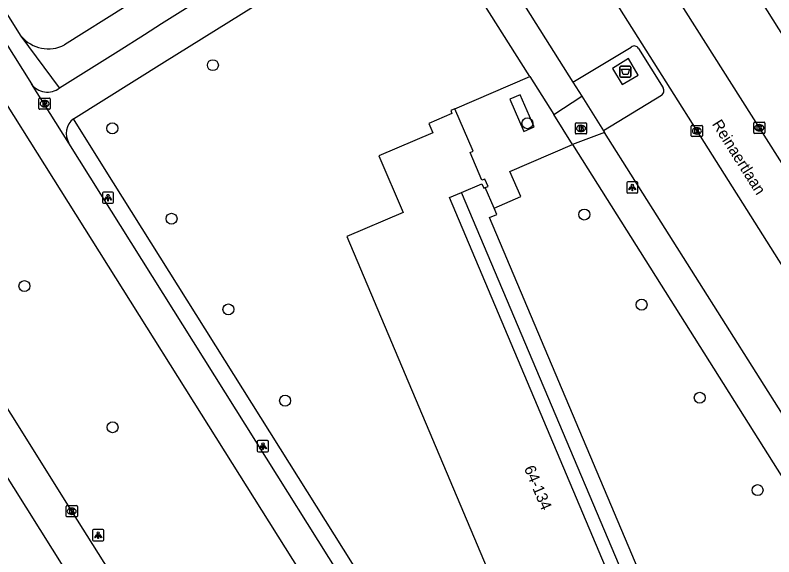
# Model space of a CAD drawing. Extents: x 160077 to 160945, y 386481 to 387498.
# Drawn here: x 160179.2 to 160246.9, y 387158.5 to 387206.8 of the extents above; entities that cross this region are included whole.
import ezdxf

# ---------------------------------------------------------------- set-up
doc = ezdxf.new("R2010")
doc.units = 0
for name, color, linetype in [('IMGEO_Afval_apart_plaats', 7, 'Continuous'), ('IMGEO_Boom', 7, 'Continuous'), ('IMGEO_Brandkraan', 7, 'Continuous'), ('IMGEO_Fietspad_gesloten', 7, 'Continuous'), ('IMGEO_Fietspad_open', 7, 'Continuous'), ('IMGEO_Kolk', 7, 'Continuous'), ('IMGEO_Lichtpunt', 7, 'Continuous'), ('IMGEO_Openbare_ruimte_label', 7, 'Continuous'), ('IMGEO_OVBaan_gesloten', 7, 'Continuous'), ('IMGEO_Pand', 7, 'Continuous'), ('IMGEO_Pand_nummerreeks', 7, 'Continuous'), ('IMGEO_Rijbaan_lokaal_open', 7, 'Continuous'), ('IMGEO_Rijbaan_regionaal_gesloten', 7, 'Continuous'), ('IMGEO_Voetpad_gesloten', 7, 'Continuous'), ('IMGEO_Voetpad_open', 7, 'Continuous')]:
    doc.layers.add(name, color=color, linetype=linetype)

msp = doc.modelspace()

# ---------------------------------------------------------------- linework, layer by layer
at = {"layer": 'IMGEO_Afval_apart_plaats'}
for p, q in [((160233.142, 387201.381), (160233.142, 387202.181)), ((160233.142, 387202.181), (160233.142, 387201.381)), ((160233.242, 387202.281), (160234.032, 387202.281)), ((160234.032, 387202.281), (160233.242, 387202.281)), ((160234.132, 387202.181), (160234.132, 387201.381)), ((160234.132, 387201.381), (160234.132, 387202.181)), ((160234.032, 387201.281), (160233.242, 387201.281)), ((160233.242, 387201.281), (160234.032, 387201.281))]:
    msp.add_line(p, q, dxfattribs=at)
msp.add_lwpolyline([(160233.285, 387201.995), (160233.989, 387201.995), (160233.84, 387201.525), (160233.434, 387201.525), (160233.285, 387201.995)], dxfattribs=at)
for centre, start, end in [((160233.242, 387202.181), 90, 180), ((160233.242, 387202.181), 90, 180), ((160234.032, 387202.181), 0, 90), ((160234.032, 387202.181), 360, 90), ((160233.242, 387201.381), 180, 270), ((160233.242, 387201.381), 180, 270), ((160234.032, 387201.381), 270, 0), ((160234.032, 387201.381), 270, 0)]:
    msp.add_arc(centre, 0.1, start, end, dxfattribs=at)
at = {"layer": 'IMGEO_Boom'}
for centre in [(160196.85, 387202.357), (160224.896, 387197.177), (160187.885, 387196.721), (160229.972, 387189.035), (160193.164, 387188.658), (160180.05, 387182.652), (160235.076, 387180.991), (160198.235, 387180.572), (160240.264, 387172.688), (160203.294, 387172.428), (160187.905, 387170.057), (160245.423, 387164.448)]:
    msp.add_circle(centre, 0.489, dxfattribs=at)
at = {"layer": 'IMGEO_Brandkraan'}
for p, q in [((160181.421, 387199.424), (160182.273, 387199.424)), ((160181.346, 387198.498), (160181.346, 387199.35)), ((160181.834, 387199.204), (160181.859, 387199.204)), ((160182.347, 387199.35), (160182.347, 387198.498)), ((160182.273, 387198.424), (160181.421, 387198.424)), ((160181.857, 387198.644), (160181.832, 387198.644)), ((160229.177, 387196.294), (160229.177, 387197.146)), ((160229.252, 387197.22), (160230.104, 387197.22)), ((160229.665, 387197), (160229.69, 387197)), ((160230.178, 387197.146), (160230.178, 387196.294)), ((160230.104, 387196.22), (160229.252, 387196.22)), ((160229.688, 387196.44), (160229.663, 387196.44))]:
    msp.add_line(p, q, dxfattribs=at)
for points in [[(160181.421, 387199.424), (160182.273, 387199.424)], [(160181.346, 387198.498), (160181.346, 387199.35)], [(160181.694, 387199.124), (160181.694, 387198.724), (160181.907, 387198.724)], [(160181.925, 387199.124), (160181.694, 387199.124)], [(160181.873, 387199.043), (160181.819, 387199.043), (160181.819, 387198.967)], [(160181.819, 387198.967), (160181.872, 387198.967)], [(160181.881, 387198.891), (160181.819, 387198.891), (160181.819, 387198.81)], [(160181.819, 387198.81), (160181.881, 387198.81)], [(160182.347, 387199.35), (160182.347, 387198.498)], [(160182.273, 387198.424), (160181.421, 387198.424)], [(160229.177, 387196.294), (160229.177, 387197.146)], [(160229.252, 387197.22), (160230.104, 387197.22)], [(160229.525, 387196.92), (160229.525, 387196.52), (160229.738, 387196.52)], [(160229.756, 387196.92), (160229.525, 387196.92)], [(160229.704, 387196.839), (160229.65, 387196.839), (160229.65, 387196.763)], [(160229.65, 387196.763), (160229.703, 387196.763)], [(160230.178, 387197.146), (160230.178, 387196.294)], [(160230.104, 387196.22), (160229.252, 387196.22)], [(160229.712, 387196.687), (160229.65, 387196.687), (160229.65, 387196.606)], [(160229.65, 387196.606), (160229.712, 387196.606)]]:
    msp.add_lwpolyline(points, dxfattribs=at)
for centre, radius, start, end in [((160181.423, 387199.348), 0.0765, 91.55205, 178.44795), ((160181.423, 387199.348), 0.0765, 91.55205, 178.44795), ((160182.271, 387199.348), 0.0765, 1.55205, 88.44795), ((160182.271, 387199.348), 0.0765, 1.55205, 88.44795), ((160181.874, 387199.005), 0.0379, 267.82845, 90.93552), ((160181.882, 387198.85), 0.0404, 269.87594, 90.50774), ((160181.913, 387198.975), 0.251, 268.66757, 293.53466), ((160181.929, 387198.979), 0.145, 59.4692, 91.53667), ((160181.954, 387199.026), 0.0922, 285.51372, 58.15012), ((160181.959, 387198.834), 0.105, 301.31148, 78.98903), ((160181.423, 387198.5), 0.0765, 181.55205, 268.44795), ((160181.423, 387198.5), 0.0765, 181.55205, 268.44795), ((160182.271, 387198.5), 0.0765, 271.55205, 358.44795), ((160182.271, 387198.5), 0.0765, 271.55205, 358.44795), ((160229.254, 387197.144), 0.0765, 91.55205, 178.44795), ((160229.254, 387197.144), 0.0765, 91.55205, 178.44795), ((160229.705, 387196.801), 0.0379, 267.82845, 90.93552), ((160229.76, 387196.775), 0.145, 59.4692, 91.53667), ((160229.785, 387196.822), 0.0922, 285.51372, 58.15012), ((160229.79, 387196.63), 0.105, 301.31148, 78.98903), ((160230.102, 387197.144), 0.0765, 1.55205, 88.44795), ((160230.102, 387197.144), 0.0765, 1.55205, 88.44795), ((160229.254, 387196.296), 0.0765, 181.55205, 268.44795), ((160229.254, 387196.296), 0.0765, 181.55205, 268.44795), ((160229.713, 387196.646), 0.0404, 269.87594, 90.50774), ((160229.744, 387196.771), 0.251, 268.66757, 293.53466), ((160230.102, 387196.296), 0.0765, 271.55205, 358.44795), ((160230.102, 387196.296), 0.0765, 271.55205, 358.44795)]:
    msp.add_arc(centre, radius, start, end, dxfattribs=at)
for centre, major_axis, ratio, start_param, end_param in [((160181.833, 387198.924), (-0.387, 0.002), 0.722429, 4.712389, 7.853982), ((160181.858, 387198.924), (-0.39, 0.002), 0.717154, 1.570796, 4.712389), ((160229.664, 387196.72), (-0.387, 0.002), 0.722429, 4.712389, 7.853982), ((160229.689, 387196.72), (-0.39, 0.002), 0.717154, 1.570796, 4.712389)]:
    msp.add_ellipse(centre, major_axis=major_axis, ratio=ratio, start_param=start_param, end_param=end_param, dxfattribs=at)
at = {"layer": 'IMGEO_Fietspad_gesloten'}
for points in [[(160139.072, 387265.739), (160141.59, 387262.907), (160159.923, 387233.732), (160180.666, 387200.687)], [(160136.342, 387264.367), (160139.625, 387260.516), (160141.252, 387258.195), (160161.015, 387226.623), (160198.581, 387166.822), (160220.594, 387131.778)], [(160184.005, 387195.408), (160180.666, 387200.687)], [(160223.762, 387132.086), (160222.926, 387133.369), (160185.895, 387192.376), (160184.005, 387195.408)]]:
    msp.add_lwpolyline(points, dxfattribs=at)
at = {"layer": 'IMGEO_Fietspad_open'}
for points in [[(160183.16, 387200.334), (160188.403, 387203.609), (160190.744, 387205.097), (160192.259, 387206.087), (160230.858, 387230.252)], [(160184.423, 387197.569), (160192.529, 387202.664), (160211.947, 387214.771), (160215.32, 387216.878)]]:
    msp.add_lwpolyline(points, dxfattribs=at)
for centre, radius, start, end in [((160182.079, 387201.681), 1.727, 215.11937, 308.7684), ((160185.453, 387196.249), 1.674, 127.96139, 210.14367)]:
    msp.add_arc(centre, radius, start, end, dxfattribs=at)
at = {"layer": 'IMGEO_Kolk'}
for p, q in [((160239.51, 387196.064), (160239.51, 387196.916)), ((160239.585, 387196.99), (160240.437, 387196.99)), ((160239.998, 387196.77), (160240.023, 387196.77)), ((160240.511, 387196.916), (160240.511, 387196.064)), ((160245.077, 387196.346), (160245.077, 387197.198)), ((160245.152, 387197.272), (160246.004, 387197.272)), ((160245.565, 387197.052), (160245.59, 387197.052)), ((160246.078, 387197.198), (160246.078, 387196.346)), ((160240.021, 387196.21), (160239.996, 387196.21)), ((160246.004, 387196.272), (160245.152, 387196.272)), ((160245.588, 387196.492), (160245.563, 387196.492)), ((160240.437, 387195.99), (160239.585, 387195.99)), ((160183.765, 387162.137), (160183.765, 387162.989)), ((160183.84, 387163.063), (160184.692, 387163.063)), ((160184.766, 387162.989), (160184.766, 387162.137)), ((160184.276, 387162.283), (160184.251, 387162.283)), ((160184.253, 387162.843), (160184.278, 387162.843)), ((160184.692, 387162.063), (160183.84, 387162.063))]:
    msp.add_line(p, q, dxfattribs=at)
for points in [[(160239.51, 387196.064), (160239.51, 387196.916)], [(160239.585, 387196.99), (160240.437, 387196.99)], [(160240.511, 387196.916), (160240.511, 387196.064)], [(160245.077, 387196.346), (160245.077, 387197.198)], [(160245.152, 387197.272), (160246.004, 387197.272)], [(160245.398, 387196.972), (160245.521, 387196.972), (160245.521, 387196.821), (160245.651, 387196.972), (160245.815, 387196.972), (160245.669, 387196.821), (160245.822, 387196.572), (160245.67, 387196.572), (160245.585, 387196.736), (160245.521, 387196.669), (160245.521, 387196.572), (160245.398, 387196.572), (160245.398, 387196.972)], [(160246.078, 387197.198), (160246.078, 387196.346)], [(160239.831, 387196.69), (160239.954, 387196.69), (160239.954, 387196.539), (160240.084, 387196.69), (160240.248, 387196.69), (160240.102, 387196.539), (160240.255, 387196.29), (160240.103, 387196.29), (160240.018, 387196.454), (160239.954, 387196.387), (160239.954, 387196.29), (160239.831, 387196.29), (160239.831, 387196.69)], [(160246.004, 387196.272), (160245.152, 387196.272)], [(160240.437, 387195.99), (160239.585, 387195.99)], [(160183.765, 387162.137), (160183.765, 387162.989)], [(160183.84, 387163.063), (160184.692, 387163.063)], [(160184.766, 387162.989), (160184.766, 387162.137)], [(160184.086, 387162.763), (160184.209, 387162.763), (160184.209, 387162.612), (160184.339, 387162.763), (160184.503, 387162.763), (160184.357, 387162.612), (160184.51, 387162.363), (160184.358, 387162.363), (160184.273, 387162.527), (160184.209, 387162.46), (160184.209, 387162.363), (160184.086, 387162.363), (160184.086, 387162.763)], [(160184.692, 387162.063), (160183.84, 387162.063)]]:
    msp.add_lwpolyline(points, dxfattribs=at)
for centre, start, end in [((160239.587, 387196.914), 91.55205, 178.44795), ((160239.587, 387196.914), 91.55205, 178.44795), ((160240.435, 387196.914), 1.55205, 88.44795), ((160240.435, 387196.914), 1.55205, 88.44795), ((160245.154, 387197.196), 91.55205, 178.44795), ((160245.154, 387197.196), 91.55205, 178.44795), ((160246.002, 387197.196), 1.55205, 88.44795), ((160246.002, 387197.196), 1.55205, 88.44795), ((160239.587, 387196.066), 181.55205, 268.44795), ((160239.587, 387196.066), 181.55205, 268.44795), ((160240.435, 387196.066), 271.55205, 358.44795), ((160240.435, 387196.066), 271.55205, 358.44795), ((160245.154, 387196.348), 181.55205, 268.44795), ((160245.154, 387196.348), 181.55205, 268.44795), ((160246.002, 387196.348), 271.55205, 358.44795), ((160246.002, 387196.348), 271.55205, 358.44795), ((160183.842, 387162.987), 91.55205, 178.44795), ((160183.842, 387162.987), 91.55205, 178.44795), ((160184.69, 387162.987), 1.55205, 88.44795), ((160184.69, 387162.987), 1.55205, 88.44795), ((160183.842, 387162.139), 181.55205, 268.44795), ((160183.842, 387162.139), 181.55205, 268.44795), ((160184.69, 387162.139), 271.55205, 358.44795), ((160184.69, 387162.139), 271.55205, 358.44795)]:
    msp.add_arc(centre, 0.0765, start, end, dxfattribs=at)
for centre, major_axis, ratio, start_param, end_param in [((160239.997, 387196.49), (-0.387, 0.002), 0.722429, 4.712389, 7.853982), ((160240.022, 387196.49), (-0.39, 0.002), 0.717154, 1.570796, 4.712389), ((160245.564, 387196.772), (-0.387, 0.002), 0.722429, 4.712389, 7.853982), ((160245.589, 387196.772), (-0.39, 0.002), 0.717154, 1.570796, 4.712389), ((160184.252, 387162.563), (-0.387, 0.002), 0.722429, 4.712389, 7.853982), ((160184.277, 387162.563), (-0.39, 0.002), 0.717154, 1.570796, 4.712389)]:
    msp.add_ellipse(centre, major_axis=major_axis, ratio=ratio, start_param=start_param, end_param=end_param, dxfattribs=at)
at = {"layer": 'IMGEO_Lichtpunt'}
for p, q in [((160233.753, 387191.856), (160233.753, 387191.049)), ((160233.753, 387191.856), (160233.753, 387191.049)), ((160234.655, 387191.951), (160233.847, 387191.951)), ((160234.655, 387191.951), (160233.847, 387191.951)), ((160234.749, 387191.049), (160234.749, 387191.856)), ((160234.749, 387191.049), (160234.749, 387191.856)), ((160187.006, 387190.938), (160187.006, 387190.131)), ((160187.006, 387190.938), (160187.006, 387190.131)), ((160187.908, 387191.033), (160187.1, 387191.033)), ((160187.908, 387191.033), (160187.1, 387191.033)), ((160188.002, 387190.131), (160188.002, 387190.938)), ((160188.002, 387190.131), (160188.002, 387190.938)), ((160233.847, 387190.955), (160234.655, 387190.955)), ((160233.847, 387190.955), (160234.655, 387190.955)), ((160187.1, 387190.037), (160187.908, 387190.037)), ((160187.1, 387190.037), (160187.908, 387190.037)), ((160200.812, 387168.77), (160200.812, 387167.963)), ((160200.812, 387168.77), (160200.812, 387167.963)), ((160201.714, 387168.865), (160200.906, 387168.865)), ((160201.714, 387168.865), (160200.906, 387168.865)), ((160201.808, 387167.963), (160201.808, 387168.77)), ((160201.808, 387167.963), (160201.808, 387168.77)), ((160200.906, 387167.869), (160201.714, 387167.869)), ((160200.906, 387167.869), (160201.714, 387167.869)), ((160187.026, 387160.928), (160186.218, 387160.928)), ((160187.026, 387160.928), (160186.218, 387160.928)), ((160186.124, 387160.833), (160186.124, 387160.026)), ((160186.124, 387160.833), (160186.124, 387160.026)), ((160187.12, 387160.026), (160187.12, 387160.833)), ((160187.12, 387160.026), (160187.12, 387160.833)), ((160186.218, 387159.932), (160187.026, 387159.932)), ((160186.218, 387159.932), (160187.026, 387159.932))]:
    msp.add_line(p, q, dxfattribs=at)
for points in [[(160234.127, 387191.52), (160234.166, 387191.492), (160233.978, 387191.23), (160233.94, 387191.257), (160234.127, 387191.52)], [(160234.229, 387191.472), (160234.276, 387191.472), (160234.276, 387191.15), (160234.229, 387191.15), (160234.229, 387191.472)], [(160234.339, 387191.492), (160234.377, 387191.519), (160234.564, 387191.257), (160234.525, 387191.229), (160234.339, 387191.492)], [(160187.38, 387190.602), (160187.419, 387190.574), (160187.231, 387190.312), (160187.193, 387190.339), (160187.38, 387190.602)], [(160187.482, 387190.554), (160187.529, 387190.554), (160187.529, 387190.232), (160187.482, 387190.232), (160187.482, 387190.554)], [(160187.592, 387190.574), (160187.63, 387190.601), (160187.817, 387190.339), (160187.778, 387190.311), (160187.592, 387190.574)], [(160201.186, 387168.434), (160201.225, 387168.406), (160201.037, 387168.144), (160200.999, 387168.171), (160201.186, 387168.434)], [(160201.288, 387168.386), (160201.335, 387168.386), (160201.335, 387168.064), (160201.288, 387168.064), (160201.288, 387168.386)], [(160201.398, 387168.406), (160201.436, 387168.433), (160201.623, 387168.171), (160201.584, 387168.143), (160201.398, 387168.406)], [(160186.498, 387160.497), (160186.537, 387160.469), (160186.349, 387160.207), (160186.311, 387160.234), (160186.498, 387160.497)], [(160186.6, 387160.449), (160186.647, 387160.449), (160186.647, 387160.127), (160186.6, 387160.127), (160186.6, 387160.449)], [(160186.71, 387160.469), (160186.748, 387160.496), (160186.935, 387160.234), (160186.896, 387160.206), (160186.71, 387160.469)]]:
    msp.add_lwpolyline(points, dxfattribs=at)
for centre in [(160234.252, 387191.654), (160187.505, 387190.736), (160201.311, 387168.568), (160186.623, 387160.631)]:
    msp.add_circle(centre, 0.0994, dxfattribs=at)
for centre, start, end in [((160233.847, 387191.856), 90, 180), ((160233.847, 387191.856), 90, 180), ((160234.655, 387191.856), 0, 90), ((160234.655, 387191.856), 0, 90), ((160187.1, 387190.938), 90, 180), ((160187.1, 387190.938), 90, 180), ((160187.908, 387190.938), 0, 90), ((160187.908, 387190.938), 0, 90), ((160233.847, 387191.049), 180, 270), ((160233.847, 387191.049), 180, 270), ((160234.655, 387191.049), 270, 0), ((160234.655, 387191.049), 270, 360), ((160187.1, 387190.131), 180, 270), ((160187.1, 387190.131), 180, 270), ((160187.908, 387190.131), 270, 0), ((160187.908, 387190.131), 270, 360), ((160200.906, 387168.77), 90, 180), ((160200.906, 387168.77), 90, 180), ((160201.714, 387168.77), 0, 90), ((160201.714, 387168.77), 0, 90), ((160200.906, 387167.963), 180, 270), ((160200.906, 387167.963), 180, 270), ((160201.714, 387167.963), 270, 0), ((160201.714, 387167.963), 270, 360), ((160186.218, 387160.833), 90, 180), ((160186.218, 387160.833), 90, 180), ((160187.026, 387160.833), 0, 90), ((160187.026, 387160.833), 0, 90), ((160186.218, 387160.026), 180, 270), ((160186.218, 387160.026), 180, 270), ((160187.026, 387160.026), 270, 0), ((160187.026, 387160.026), 270, 360)]:
    msp.add_arc(centre, 0.0946, start, end, dxfattribs=at)
at = {"layer": 'IMGEO_OVBaan_gesloten'}
msp.add_lwpolyline([(160248.244, 387054.606), (160224.562, 387092.222), (160199.952, 387131.452), (160165.124, 387186.911), (160140.996, 387225.337)], dxfattribs=at)
at = {"layer": 'IMGEO_Pand'}
for points in [[(160218.439, 387198.463), (160218.06, 387198.303), (160218.173, 387198.038), (160216.109, 387197.157), (160216.461, 387196.334), (160211.661, 387194.284), (160213.806, 387189.204), (160208.795, 387187.088), (160230.812, 387134.941), (160235.799, 387137.046)], [(160221.144, 387191.439), (160221.39, 387191.545), (160221.11, 387192.199), (160220.847, 387192.086), (160219.791, 387194.56), (160220.057, 387194.673), (160218.439, 387198.463)], [(160219.015, 387190.999), (160220.84, 387191.779), (160221.011, 387191.382), (160221.144, 387191.439)], [(160240.799, 387139.494), (160239.693, 387139.027), (160217.943, 387190.541), (160219.015, 387190.999)]]:
    msp.add_lwpolyline(points, dxfattribs=at)
at = {"layer": 'IMGEO_Rijbaan_lokaal_open'}
for points in [[(160227.566, 387216.245), (160250.335, 387180.106), (160272.691, 387144.583)], [(160233.409, 387215.988), (160250.479, 387189.032), (160269.264, 387159.297)]]:
    msp.add_lwpolyline(points, dxfattribs=at)
at = {"layer": 'IMGEO_Rijbaan_regionaal_gesloten'}
msp.add_lwpolyline([(160206.665, 387126.914), (160204.971, 387129.647), (160194.633, 387146.088), (160184.266, 387162.563), (160173.425, 387179.881), (160169.034, 387186.827)], dxfattribs=at)
at = {"layer": 'IMGEO_Voetpad_gesloten'}
msp.add_lwpolyline([(160233.923, 387202.947), (160232.486, 387202.055), (160233.357, 387200.633), (160234.778, 387201.472), (160233.923, 387202.947)], dxfattribs=at)
at = {"layer": 'IMGEO_Voetpad_open'}
for points in [[(160179.769, 387204.942), (160161.126, 387234.638), (160142.864, 387263.696), (160139.615, 387268.878)], [(160226.36, 387220.948), (160226.349, 387220.891), (160226.316, 387220.766), (160226.273, 387220.645), (160226.218, 387220.528), (160226.154, 387220.417), (160226.08, 387220.311), (160225.996, 387220.213), (160225.904, 387220.123), (160225.805, 387220.041), (160219.401, 387215.993), (160228.959, 387200.845)], [(160225.112, 387201.343), (160215.32, 387216.878)], [(160249.845, 387201.573), (160240.736, 387216.058)], [(160196.955, 387212.573), (160189.118, 387207.631), (160183.618, 387204.16)], [(160183.16, 387200.334), (160179.769, 387204.942)], [(160228.959, 387200.845), (160234.151, 387203.974)], [(160234.812, 387203.853), (160236.996, 387200.349)], [(160218.439, 387198.463), (160225.112, 387201.343)], [(160225.112, 387201.343), (160227.248, 387197.953)], [(160228.959, 387200.845), (160229.747, 387199.595)], [(160225.498, 387196.87), (160224.257, 387199.721), (160223.319, 387199.329), (160224.565, 387196.449), (160225.498, 387196.87)], [(160227.248, 387197.953), (160229.747, 387199.595)], [(160229.747, 387199.595), (160231.696, 387196.505)], [(160236.841, 387199.663), (160231.696, 387196.505)], [(160225.336, 387132.427), (160224.187, 387134.187), (160187.198, 387193.134), (160184.423, 387197.569)], [(160228.93, 387195.285), (160227.248, 387197.953)], [(160231.786, 387196.362), (160228.93, 387195.285)], [(160231.696, 387196.505), (160231.786, 387196.362)], [(160261.521, 387149.245), (160231.786, 387196.362)], [(160221.92, 387189.603), (160224.298, 387190.633), (160223.332, 387192.863), (160228.93, 387195.285)], [(160228.93, 387195.285), (160264.195, 387139.299)], [(160221.92, 387189.603), (160221.144, 387191.439)], [(160240.799, 387139.494), (160219.015, 387190.999)], [(160246.804, 387128.394), (160244.052, 387134.973), (160245.413, 387135.571), (160243.75, 387139.494), (160243.14, 387140.937), (160241.928, 387140.436), (160221.518, 387188.766), (160222.159, 387189.036), (160221.92, 387189.603)]]:
    msp.add_lwpolyline(points, dxfattribs=at)
for centre, radius, start, end in [((160182.179, 387206.939), 3.129, 219.64444, 297.38667), ((160234.428, 387203.62), 0.449, 31.21973, 128.0333), ((160236.58, 387200.082), 0.494, 301.88811, 32.6478)]:
    msp.add_arc(centre, radius, start, end, dxfattribs=at)

# ---------------------------------------------------------------- texts
at = {"layer": 'IMGEO_Openbare_ruimte_label'}
msp.add_text('Reinaertlaan', height=1, rotation=302.2119, dxfattribs=at).set_placement((160241.323, 387197.107))
at = {"layer": 'IMGEO_Pand_nummerreeks'}
msp.add_text('64-134', height=1, rotation=292.89022, dxfattribs=at).set_placement((160224.576, 387166.399))

doc.saveas('drawing.dxf')
